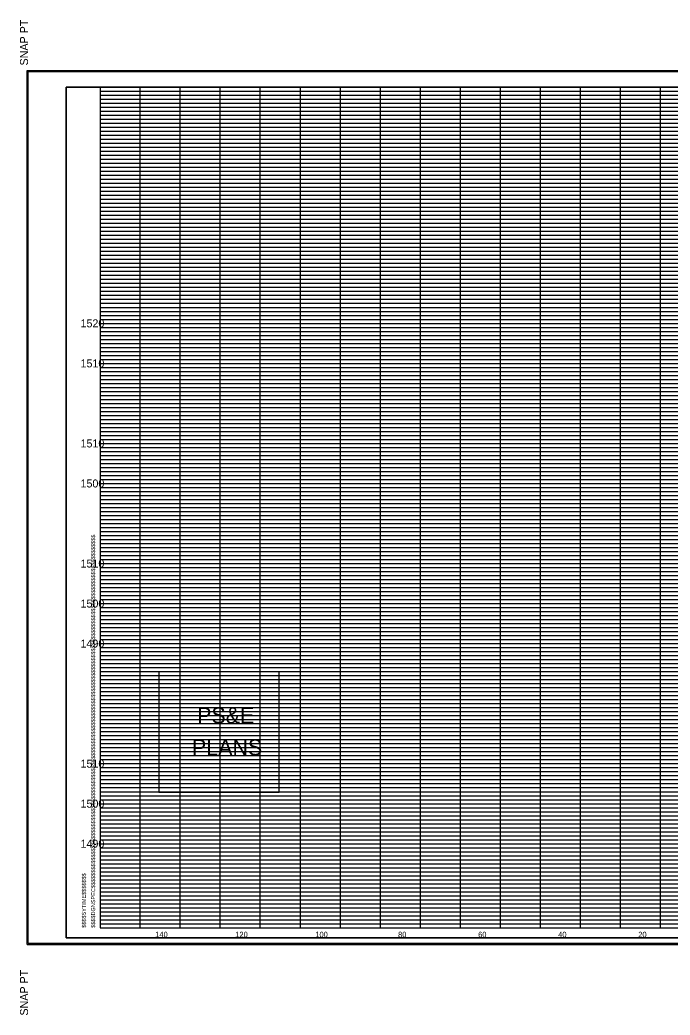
# Model space of a CAD drawing. Extents: x 980 to 1324, y 978 to 1497.
# Drawn here: x 979.9 to 1142.4, y 1248.2 to 1496.8 of the extents above; entities that cross this region are included whole.
import ezdxf

# ---------------------------------------------------------------- set-up
doc = ezdxf.new("R2010")
doc.units = 0
for name, color, linetype in [('DESIGN - SHEET - Corner Text', 7, 'Continuous'), ('DESIGN - SHEET - Light Grid', 7, 'Continuous'), ('DESIGN - SHEET - Linework', 7, 'Continuous'), ('DESIGN - SHEET - Plot Shape', 7, 'Continuous'), ('DESIGN - TYPICAL - Text', 7, 'Continuous')]:
    doc.layers.add(name, color=color, linetype=linetype)

# ---------------------------------------------------------------- blocks, each defined once
blk = doc.blocks.new('XSTSHT')
at = {"layer": 'DESIGN - SHEET - Light Grid'}
for p, q in [((0, 20.9), (8, 20.9)), ((8, 20.9), (16, 20.9)), ((0, 20.8), (8, 20.8)), ((0, 20.7), (8, 20.7)), ((8, 20.8), (16, 20.8)), ((8, 20.7), (16, 20.7)), ((0, 20.6), (8, 20.6)), ((0, 20.5), (8, 20.5)), ((0, 20.4), (8, 20.4)), ((8, 20.6), (16, 20.6)), ((8, 20.5), (16, 20.5)), ((8, 20.4), (16, 20.4)), ((0, 20.3), (8, 20.3)), ((0, 20.2), (8, 20.2)), ((8, 20.3), (16, 20.3)), ((8, 20.2), (16, 20.2)), ((0, 20.1), (8, 20.1)), ((0, 19.9), (8, 19.9)), ((8, 20.1), (16, 20.1)), ((8, 19.9), (16, 19.9)), ((0, 19.8), (8, 19.8)), ((0, 19.7), (8, 19.7)), ((8, 19.8), (16, 19.8)), ((8, 19.7), (16, 19.7)), ((0, 19.6), (8, 19.6)), ((0, 19.5), (8, 19.5)), ((0, 19.4), (8, 19.4)), ((8, 19.6), (16, 19.6)), ((8, 19.5), (16, 19.5)), ((8, 19.4), (16, 19.4)), ((0, 19.3), (8, 19.3)), ((0, 19.2), (8, 19.2)), ((8, 19.3), (16, 19.3)), ((8, 19.2), (16, 19.2)), ((0, 19.1), (8, 19.1)), ((0, 18.9), (8, 18.9)), ((8, 19.1), (16, 19.1)), ((8, 18.9), (16, 18.9)), ((0, 18.8), (8, 18.8)), ((0, 18.7), (8, 18.7)), ((8, 18.8), (16, 18.8)), ((8, 18.7), (16, 18.7)), ((0, 18.6), (8, 18.6)), ((0, 18.5), (8, 18.5)), ((0, 18.4), (8, 18.4)), ((8, 18.6), (16, 18.6)), ((8, 18.5), (16, 18.5)), ((8, 18.4), (16, 18.4)), ((0, 18.3), (8, 18.3)), ((0, 18.2), (8, 18.2)), ((8, 18.3), (16, 18.3)), ((8, 18.2), (16, 18.2)), ((0, 18.1), (8, 18.1)), ((8, 18.1), (16, 18.1)), ((0, 17.9), (8, 17.9)), ((0, 17.8), (8, 17.8)), ((0, 17.7), (8, 17.7)), ((8, 17.9), (16, 17.9)), ((8, 17.8), (16, 17.8)), ((8, 17.7), (16, 17.7)), ((0, 17.6), (8, 17.6)), ((0, 17.5), (8, 17.5)), ((8, 17.6), (16, 17.6)), ((8, 17.5), (16, 17.5)), ((0, 17.4), (8, 17.4)), ((0, 17.3), (8, 17.3)), ((0, 17.2), (8, 17.2)), ((8, 17.4), (16, 17.4)), ((8, 17.3), (16, 17.3)), ((8, 17.2), (16, 17.2)), ((0, 17.1), (8, 17.1)), ((8, 17.1), (16, 17.1)), ((0, 16.9), (8, 16.9)), ((0, 16.8), (8, 16.8)), ((0, 16.7), (8, 16.7)), ((8, 16.9), (16, 16.9)), ((8, 16.8), (16, 16.8)), ((8, 16.7), (16, 16.7)), ((0, 16.6), (8, 16.6)), ((0, 16.5), (8, 16.5)), ((8, 16.6), (16, 16.6)), ((8, 16.5), (16, 16.5)), ((0, 16.4), (8, 16.4)), ((0, 16.3), (8, 16.3)), ((0, 16.2), (8, 16.2)), ((8, 16.4), (16, 16.4)), ((8, 16.3), (16, 16.3)), ((8, 16.2), (16, 16.2)), ((0, 16.1), (8, 16.1)), ((8, 16.1), (16, 16.1)), ((0, 15.9), (8, 15.9)), ((0, 15.8), (8, 15.8)), ((0, 15.7), (8, 15.7)), ((8, 15.9), (16, 15.9)), ((8, 15.8), (16, 15.8)), ((8, 15.7), (16, 15.7)), ((0, 15.6), (8, 15.6)), ((0, 15.5), (8, 15.5)), ((8, 15.6), (16, 15.6)), ((8, 15.5), (16, 15.5)), ((0, 15.4), (8, 15.4)), ((0, 15.3), (8, 15.3)), ((0, 15.2), (8, 15.2)), ((8, 15.4), (16, 15.4)), ((8, 15.3), (16, 15.3)), ((8, 15.2), (16, 15.2)), ((0, 15.1), (8, 15.1)), ((8, 15.1), (16, 15.1)), ((0, 14.9), (8, 14.9)), ((0, 14.8), (8, 14.8)), ((0, 14.7), (8, 14.7)), ((8, 14.9), (16, 14.9)), ((8, 14.8), (16, 14.8)), ((8, 14.7), (16, 14.7)), ((0, 14.6), (8, 14.6)), ((0, 14.5), (8, 14.5)), ((8, 14.6), (16, 14.6)), ((8, 14.5), (16, 14.5)), ((0, 14.4), (8, 14.4)), ((0, 14.3), (8, 14.3)), ((0, 14.2), (8, 14.2)), ((8, 14.4), (16, 14.4)), ((8, 14.3), (16, 14.3)), ((8, 14.2), (16, 14.2)), ((0, 14.1), (8, 14.1)), ((8, 14.1), (16, 14.1)), ((0, 13.9), (8, 13.9)), ((0, 13.8), (8, 13.8)), ((0, 13.7), (8, 13.7)), ((8, 13.9), (16, 13.9)), ((8, 13.8), (16, 13.8)), ((8, 13.7), (16, 13.7)), ((0, 13.6), (8, 13.6)), ((0, 13.5), (8, 13.5)), ((8, 13.6), (16, 13.6)), ((8, 13.5), (16, 13.5)), ((0, 13.4), (8, 13.4)), ((0, 13.3), (8, 13.3)), ((0, 13.2), (8, 13.2)), ((8, 13.4), (16, 13.4)), ((8, 13.3), (16, 13.3)), ((8, 13.2), (16, 13.2)), ((0, 13.1), (8, 13.1)), ((8, 13.1), (16, 13.1)), ((0, 12.9), (8, 12.9)), ((0, 12.8), (8, 12.8)), ((0, 12.7), (8, 12.7)), ((8, 12.9), (16, 12.9)), ((8, 12.8), (16, 12.8)), ((8, 12.7), (16, 12.7)), ((0, 12.6), (8, 12.6)), ((0, 12.5), (8, 12.5)), ((8, 12.6), (16, 12.6)), ((8, 12.5), (16, 12.5)), ((0, 12.4), (8, 12.4)), ((0, 12.3), (8, 12.3)), ((0, 12.2), (8, 12.2)), ((8, 12.4), (16, 12.4)), ((8, 12.3), (16, 12.3)), ((8, 12.2), (16, 12.2)), ((0, 12.1), (8, 12.1)), ((8, 12.1), (16, 12.1)), ((0, 11.9), (8, 11.9)), ((0, 11.8), (8, 11.8)), ((0, 11.7), (8, 11.7)), ((8, 11.9), (16, 11.9)), ((8, 11.8), (16, 11.8)), ((8, 11.7), (16, 11.7)), ((0, 11.6), (8, 11.6)), ((0, 11.5), (8, 11.5)), ((8, 11.6), (16, 11.6)), ((8, 11.5), (16, 11.5)), ((0, 11.4), (8, 11.4)), ((0, 11.3), (8, 11.3)), ((0, 11.2), (8, 11.2)), ((8, 11.4), (16, 11.4)), ((8, 11.3), (16, 11.3)), ((8, 11.2), (16, 11.2)), ((0, 11.1), (8, 11.1)), ((8, 11.1), (16, 11.1)), ((0, 10.9), (8, 10.9)), ((0, 10.8), (8, 10.8)), ((0, 10.7), (8, 10.7)), ((8, 10.9), (16, 10.9)), ((8, 10.8), (16, 10.8)), ((8, 10.7), (16, 10.7)), ((0, 10.6), (8, 10.6)), ((0, 10.5), (8, 10.5)), ((8, 10.6), (16, 10.6)), ((8, 10.5), (16, 10.5)), ((0, 10.4), (8, 10.4)), ((0, 10.3), (8, 10.3)), ((0, 10.2), (8, 10.2)), ((8, 10.4), (16, 10.4)), ((8, 10.3), (16, 10.3)), ((8, 10.2), (16, 10.2)), ((0, 10.1), (8, 10.1)), ((8, 10.1), (16, 10.1)), ((0, 9.9), (8, 9.9)), ((0, 9.8), (8, 9.8)), ((0, 9.7), (8, 9.7)), ((8, 9.9), (16, 9.9)), ((8, 9.8), (16, 9.8)), ((8, 9.7), (16, 9.7)), ((0, 9.6), (8, 9.6)), ((0, 9.5), (8, 9.5)), ((8, 9.6), (16, 9.6)), ((8, 9.5), (16, 9.5)), ((0, 9.4), (8, 9.4)), ((0, 9.3), (8, 9.3)), ((0, 9.2), (8, 9.2)), ((8, 9.4), (16, 9.4)), ((8, 9.3), (16, 9.3)), ((8, 9.2), (16, 9.2)), ((0, 9.1), (8, 9.1)), ((8, 9.1), (16, 9.1)), ((0, 8.9), (8, 8.9)), ((0, 8.8), (8, 8.8)), ((8, 8.9), (16, 8.9)), ((8, 8.8), (16, 8.8)), ((0, 8.7), (8, 8.7)), ((0, 8.6), (8, 8.6)), ((0, 8.5), (8, 8.5)), ((8, 8.7), (16, 8.7)), ((8, 8.6), (16, 8.6)), ((8, 8.5), (16, 8.5)), ((0, 8.4), (8, 8.4)), ((0, 8.3), (8, 8.3)), ((8, 8.4), (16, 8.4)), ((8, 8.3), (16, 8.3)), ((0, 8.2), (8, 8.2)), ((0, 8.1), (8, 8.1)), ((8, 8.2), (16, 8.2)), ((8, 8.1), (16, 8.1)), ((0, 7.9), (8, 7.9)), ((0, 7.8), (8, 7.8)), ((8, 7.9), (16, 7.9)), ((8, 7.8), (16, 7.8)), ((0, 7.7), (8, 7.7)), ((0, 7.6), (8, 7.6)), ((0, 7.5), (8, 7.5)), ((8, 7.7), (16, 7.7)), ((8, 7.6), (16, 7.6)), ((8, 7.5), (16, 7.5)), ((0, 7.4), (8, 7.4)), ((0, 7.3), (8, 7.3)), ((8, 7.4), (16, 7.4)), ((8, 7.3), (16, 7.3)), ((0, 7.2), (8, 7.2)), ((0, 7.1), (8, 7.1)), ((8, 7.2), (16, 7.2)), ((8, 7.1), (16, 7.1)), ((0, 6.9), (8, 6.9)), ((0, 6.8), (8, 6.8)), ((8, 6.9), (16, 6.9)), ((8, 6.8), (16, 6.8)), ((0, 6.7), (8, 6.7)), ((0, 6.6), (8, 6.6)), ((0, 6.5), (8, 6.5)), ((8, 6.7), (16, 6.7)), ((8, 6.6), (16, 6.6)), ((8, 6.5), (16, 6.5)), ((0, 6.4), (8, 6.4)), ((0, 6.3), (8, 6.3)), ((8, 6.4), (16, 6.4)), ((8, 6.3), (16, 6.3)), ((0, 6.2), (8, 6.2)), ((0, 6.1), (8, 6.1)), ((8, 6.2), (16, 6.2)), ((8, 6.1), (16, 6.1)), ((0, 5.9), (8, 5.9)), ((0, 5.8), (8, 5.8)), ((8, 5.9), (16, 5.9)), ((8, 5.8), (16, 5.8)), ((0, 5.7), (8, 5.7)), ((0, 5.6), (8, 5.6)), ((0, 5.5), (8, 5.5)), ((8, 5.7), (16, 5.7)), ((8, 5.6), (16, 5.6)), ((8, 5.5), (16, 5.5)), ((0, 5.4), (8, 5.4)), ((0, 5.3), (8, 5.3)), ((8, 5.4), (16, 5.4)), ((8, 5.3), (16, 5.3)), ((0, 5.2), (8, 5.2)), ((0, 5.1), (8, 5.1)), ((8, 5.2), (16, 5.2)), ((8, 5.1), (16, 5.1)), ((0, 4.9), (8, 4.9)), ((0, 4.8), (8, 4.8)), ((8, 4.9), (16, 4.9)), ((8, 4.8), (16, 4.8)), ((0, 4.7), (8, 4.7)), ((0, 4.6), (8, 4.6)), ((0, 4.5), (8, 4.5)), ((8, 4.7), (16, 4.7)), ((8, 4.6), (16, 4.6)), ((8, 4.5), (16, 4.5)), ((0, 4.4), (8, 4.4)), ((0, 4.3), (8, 4.3)), ((8, 4.4), (16, 4.4)), ((8, 4.3), (16, 4.3)), ((0, 4.2), (8, 4.2)), ((0, 4.1), (8, 4.1)), ((8, 4.2), (16, 4.2)), ((8, 4.1), (16, 4.1)), ((0, 3.9), (8, 3.9)), ((0, 3.8), (8, 3.8)), ((8, 3.9), (16, 3.9)), ((8, 3.8), (16, 3.8)), ((0, 3.7), (8, 3.7)), ((0, 3.6), (8, 3.6)), ((0, 3.5), (8, 3.5)), ((8, 3.7), (16, 3.7)), ((8, 3.6), (16, 3.6)), ((8, 3.5), (16, 3.5)), ((0, 3.4), (8, 3.4)), ((0, 3.3), (8, 3.3)), ((8, 3.4), (16, 3.4)), ((8, 3.3), (16, 3.3)), ((0, 3.2), (8, 3.2)), ((0, 3.1), (8, 3.1)), ((8, 3.2), (16, 3.2)), ((8, 3.1), (16, 3.1)), ((0, 2.9), (8, 2.9)), ((0, 2.8), (8, 2.8)), ((8, 2.9), (16, 2.9)), ((8, 2.8), (16, 2.8)), ((0, 2.7), (8, 2.7)), ((0, 2.6), (8, 2.6)), ((0, 2.5), (8, 2.5)), ((8, 2.7), (16, 2.7)), ((8, 2.6), (16, 2.6)), ((8, 2.5), (16, 2.5)), ((0, 2.4), (8, 2.4)), ((0, 2.3), (8, 2.3)), ((8, 2.4), (16, 2.4)), ((8, 2.3), (16, 2.3)), ((0, 2.2), (8, 2.2)), ((0, 2.1), (8, 2.1)), ((8, 2.2), (16, 2.2)), ((8, 2.1), (16, 2.1)), ((0, 1.9), (8, 1.9)), ((0, 1.8), (8, 1.8)), ((8, 1.9), (16, 1.9)), ((8, 1.8), (16, 1.8)), ((0, 1.7), (8, 1.7)), ((0, 1.6), (8, 1.6)), ((0, 1.5), (8, 1.5)), ((8, 1.7), (16, 1.7)), ((8, 1.6), (16, 1.6)), ((8, 1.5), (16, 1.5)), ((0, 1.4), (8, 1.4)), ((0, 1.3), (8, 1.3)), ((8, 1.4), (16, 1.4)), ((8, 1.3), (16, 1.3)), ((0, 1.2), (8, 1.2)), ((0, 1.1), (8, 1.1)), ((8, 1.2), (16, 1.2)), ((8, 1.1), (16, 1.1)), ((0, 0.9), (8, 0.9)), ((0, 0.8), (8, 0.8)), ((8, 0.9), (16, 0.9)), ((8, 0.8), (16, 0.8)), ((0, 0.7), (8, 0.7)), ((0, 0.6), (8, 0.6)), ((0, 0.5), (8, 0.5)), ((8, 0.7), (16, 0.7)), ((8, 0.6), (16, 0.6)), ((8, 0.5), (16, 0.5)), ((0, 0.4), (8, 0.4)), ((0, 0.3), (8, 0.3)), ((8, 0.4), (16, 0.4)), ((8, 0.3), (16, 0.3)), ((0, 0.2), (8, 0.2)), ((0, 0.1), (8, 0.1)), ((8, 0.2), (16, 0.2)), ((8, 0.1), (16, 0.1))]:
    blk.add_line(p, q, dxfattribs=at)
at = {"layer": 'DESIGN - SHEET - Linework'}
for p, q in [((-1.823, -0.414), (-1.823, 21.414)), ((-1.823, 21.414), (32.217, 21.414)), ((1, 0), (1, 21)), ((2, 0), (2, 21)), ((3, 0), (3, 21)), ((4, 0), (4, 21)), ((5, 0), (5, 21)), ((6, 0), (6, 21)), ((7, 0), (7, 21)), ((8, 0), (8, 21)), ((9, 0), (9, 21)), ((10, 0), (10, 21)), ((11, 0), (11, 21)), ((12, 0), (12, 21)), ((13, 0), (13, 21)), ((14, 0), (14, 21)), ((0, 20), (28, 20)), ((0, 19), (32, 19)), ((0, 18), (32, 18)), ((0, 17), (32, 17)), ((0, 16), (32, 16)), ((0, 15), (32, 15)), ((0, 14), (32, 14)), ((0, 13), (32, 13)), ((0, 12), (32, 12)), ((0, 11), (32, 11)), ((0, 10), (32, 10)), ((0, 9), (32, 9)), ((0, 8), (32, 8)), ((0, 7), (32, 7)), ((0, 6), (32, 6)), ((0, 5), (32, 5)), ((0, 4), (32, 4)), ((0, 3), (32, 3)), ((0, 2), (32, 2)), ((0, 1), (32, 1)), ((-1.823, -0.414), (32.217, -0.414))]:
    blk.add_line(p, q, dxfattribs=at)
blk.add_lwpolyline([(0, 21), (0, 0), (32, 0), (32, 21), (0, 21)], dxfattribs=at)
at = {"layer": 'DESIGN - SHEET - Plot Shape'}
for points in [[(-1.803, 21.394), (32.197, 21.394), (32.197, -0.394), (-1.803, -0.394)], [(-0.85, 21), (32, 21), (32, -0.25), (-0.85, -0.25)]]:
    blk.add_lwpolyline(points, close=True, dxfattribs=at)
at = {"layer": 'DESIGN - SHEET - Corner Text'}
for s, height, p in [('  SNAP PT', 0.2, (-1.803, 21.394)), ('$$$$DGNSPEC$$$$$$$$$$$$$$$$$$$$$$$$$$$$$$$$$$$$$$$$$$$$$$$$$$$$$$$$$$$$$$$$$$$$$$$$$$$$$$$$$$$$$$$$$$$$$$$$$$$$$$$$$$$$$$$$$$$', 0.100002, (-0.126, 0)), ('$$$$SYTIME$$$$$$$', 0.1, (-0.358, 0)), ('SNAP PT  ', 0.2, (-1.803, -2.194))]:
    blk.add_text(s, height=height, rotation=90, dxfattribs=at).set_placement(p)

msp = doc.modelspace()

# ---------------------------------------------------------------- linework, layer by layer
at = {"layer": 'DESIGN - SHEET - Corner Text'}
msp.add_lwpolyline([(1014.69, 1333.9), (1014.69, 1303.9), (1044.69, 1303.9), (1044.69, 1333.9)], close=True, dxfattribs=at)
at = {"layer": 'DESIGN - SHEET - Plot Shape'}
msp.add_lwpolyline([(991.5, 1267.5), (1320, 1267.5), (1320, 1480), (991.5, 1480)], close=True, dxfattribs=at)

# ---------------------------------------------------------------- block references
at = {"layer": 'DESIGN - TYPICAL - Text', "xscale": 10, "yscale": 10}
msp.add_blockref('XSTSHT', (1000, 1270), dxfattribs=at)

# ---------------------------------------------------------------- texts
at = {"layer": 'DESIGN - SHEET - Corner Text'}
for s, p in [('PS&E', (1024.21, 1321.08)), ('PLANS', (1022.93, 1313.08))]:
    msp.add_text(s, height=4, dxfattribs=at).set_placement(p)
at = {"layer": 'DESIGN - TYPICAL - Text'}
for s, height, p in [('     1520     ', 2, (991.37, 1420)), ('     1510     ', 2, (991.37, 1410)), ('     1510     ', 2, (991.37, 1390)), ('     1500     ', 2, (991.37, 1380)), ('     1510     ', 2, (991.37, 1360)), ('     1500     ', 2, (991.37, 1350)), ('     1490     ', 2, (991.37, 1340)), ('     1510     ', 2, (991.37, 1310)), ('     1500     ', 2, (991.37, 1300)), ('     1490     ', 2, (991.37, 1290)), ('     140     ', 1.4, (1011.14, 1267.6)), ('     120     ', 1.4, (1031.14, 1267.6)), ('     100     ', 1.4, (1051.14, 1267.6)), ('     80     ', 1.4, (1071.82, 1267.6)), ('     60     ', 1.4, (1091.82, 1267.6)), ('     40     ', 1.4, (1111.82, 1267.6)), ('     20     ', 1.4, (1131.82, 1267.6))]:
    msp.add_text(s, height=height, dxfattribs=at).set_placement(p)

doc.saveas('drawing.dxf')
